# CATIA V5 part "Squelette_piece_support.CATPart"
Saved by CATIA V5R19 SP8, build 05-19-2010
Part number: Squelette_piece_support
Bounding box of the stored display mesh (mm): x -500 to 500, y 0 to 300, z 1175 to 1400
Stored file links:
  G:\EU_thinkMotion\CFAO_2010\MMS_groupe2\MMS_groupe2\OK\nrosalie\nrosalie_cfao_support_d_arme_legere_final\Squelette_piece_support.CATPart
  G:\EU_thinkMotion\CFAO_2010\MMS_groupe2\MMS_groupe2\OK\nrosalie\nrosalie_cfao_support_d_arme_legere_final\Squelette_Systeme_de_visee.CATPart
  G:\EU_thinkMotion\CFAO_2010\MMS_groupe2\MMS_groupe2\OK\nrosalie\nrosalie_cfao_support_d_arme_legere_final\nrosalie_Support_d_arme_legere.CATProduct
  G:\EU_thinkMotion\CFAO_2010\MMS_groupe2\MMS_groupe2\OK\nrosalie\nrosalie_cfao_support_d_arme_legere_final\Squelette_Colone.CATPart
  G:\EU_thinkMotion\CFAO_2010\MMS_groupe2\MMS_groupe2\OK\nrosalie\nrosalie_cfao_support_d_arme_legere_final\Bras.CATPart
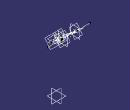
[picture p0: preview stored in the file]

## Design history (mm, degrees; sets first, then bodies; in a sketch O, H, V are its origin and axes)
External parameters (linked from other documents)
  External.Pourcentage_de_la_position_de_l_equilibrage_sur_la_piece_de_support_en_partant_axe_pivot_verticale = 10000 mm
  External.Distance_centre_cou_servant_et_pivot_bras_support = 150 mm
  External.Position_en_y_du_cou_du_servant = 300 mm
  `External.Hauteur_viseur_de_l'arme` = 1500 mm
  External.Distance_entre_les_yeux_du_servant_et_la_nuque_du_servant = 100 mm
  External.Longueur_liaison_pivot_colonne_systeme = 150 mm
Set1
  Point1 "Centre_cou_du_servant": (0, 300 {= External.Position_en_y_du_cou_du_servant}, 1400 {= `External.Hauteur_viseur_de_l'arme` -External.Distance_entre_les_yeux_du_servant_et_la_nuque_du_servant})
  Line1 "Axe_de_rotation_en_site": type Normal, RefPoint Point1, RefSkin yz-plane, Start -500, End 500
  Point2 "Centre_de_la_pivot": type OnCurve, Support Line1, RefPoint Point1, Length 150 {= External.Distance_centre_cou_servant_et_pivot_bras_support}
  Plane1 "Interphase_pivot_permettant _la_rotation_en_site": type Normal, Curve Line1, RefPoint Point2
  Point3 "Centre_liaison_pivot__systeme_de_visee": type OnCurve, Support Line7, RefPoint Point15, Length 75 {= 0.5*External.Longueur_liaison_pivot_colonne_systeme}
  Line2: type PtPt, FirstPoint Point1, SecondPoint Point3
  Point4: type OnCurve, Support Line2, Ratio 0.1 {= External.Pourcentage_de_la_position_de_l_equilibrage_sur_la_piece_de_support_en_partant_axe_pivot_verticale /100}
  Plane2: type OffsetPt, RefPlane xy-plane, RefPoint Point3
  Point5: type OnPlane, Support Plane2, RefPoint DatumPoint1, H -40, V 0, Direction (1, 0, 0)
  Point6: type OnCurve, Support Line1, RefPoint Point2, Length 10
  Line3: type PtPt, FirstPoint Point5, SecondPoint Point6
  Plane3: type Normal, Curve Line3, RefPoint Point5
  Plane4: type Normal, Curve Line3, RefPoint Point6
  Plane5: type 3Points, Element1 Point3, Element2 Point5, Element3 Point6
  Plane6: type 3Points, Element1 Point2, Element2 Point1, Element3 Point4
  Point7: type OnPlane, Support Plane6, RefPoint Point6, H 30, V 0, Direction (-1, 0, 0)
  Point8: type OnPlane, Support Plane6, RefPoint Point5, H 30, V 0, Direction (-1, 0, 0)
  Line4: type PtPt, FirstPoint Point8, SecondPoint Point7
  Point9: type OnCurve, Support Line4, Ratio 0.1 {= External.Pourcentage_de_la_position_de_l_equilibrage_sur_la_piece_de_support_en_partant_axe_pivot_verticale /100}
  Point10: type OnCurve, Support Line1, RefPoint Point1, Length 150 {= External.Distance_centre_cou_servant_et_pivot_bras_support}
  Point11: type OnCurve, Support Line1, RefPoint Point12, Length 30
  Point12: type OnCurve, Support Line1, RefPoint Point10, Length 10
  Plane7: type Normal, Curve Line1, RefPoint Point10
  Point13: type OnPlane, Support Plane2, RefPoint DatumPoint2, H 40, V 0, Direction (1, 0, 0)
  Line5: type PtPt, FirstPoint Point12, SecondPoint Point13
  Point14: type OnPlane, Support Plane2, RefPoint Point13, H 30, V 0, Direction (1, 0, 0)
  Line6: type PtPt, FirstPoint Point11, SecondPoint Point14
  Plane8: type Normal, Curve Line5, RefPoint Point13
  Plane9: type Normal, Curve Line5, RefPoint Point12
  Sketch1 on Plane7, origin (150, 0, 0), H (0, 1, 0), V (0, 0, 1)
    construction circle A1 centre (-150, 1220) radius 15
    point P1 (-150, 1220)
    spline S1 through (295.4323, 1314.2876) (-150.5609, 1234.9895) (-596.5542, 1279.5989)
    spline S2 through (304.5664, 1285.712) (-149.4391, 1205.0105) (-603.4446, 1250.4009)
    arc A2 centre (-600, 1265) radius 15 from (-596.5542, 1279.5989) to (-603.4446, 1250.4009) ccw
    point P2 (-600, 1265)
    arc A3 centre (300, 1300) radius 15 from (304.5664, 1285.712) to (295.4323, 1314.2876) ccw
    point P4 (-603.4446, 1250.4009)
    point P5 (-596.5542, 1279.5989)
    point P6 (295.4323, 1314.2876)
    point P7 (304.5664, 1285.712)
    reference projected point E1 (-150, 1220)
    reference projected point E2 (-600, 1265)
    reference projected point E3 (300, 1300)
    reference projected point E4 (300, 1300)
    point P8 (-150.5609, 1234.9895)
    point P9 (-149.4391, 1205.0105)
    point P10 (304.5664, 1285.712)
    point P11 (295.4323, 1314.2876)
    point P12 (-596.5542, 1279.5989)
    point P13 (-603.4446, 1250.4009)
    radius A2 = 15
    radius A1 = 15
    distance E3 A3 = 15
    tangency: S1 A1, A1 S2, A2 S2, S1 A2, S1 A3, S2 A3
    coincidence: P8 A1, P9 A1, P1 E1, P2 E2, P5 P12, P13 P4, P6 P11, P7 P10
    concentricity: A3 E4
  Sketch2 on Plane7, origin (150, 0, 1150.0001), H (0, 0, -1), V (0, 1, 0)
    line L1 (-150, 315) -> (-130, 315)
    line L2 (-130, 315) -> (-130, 285)
    line L3 (-130, 285) -> (-135, 285)
    line L4 (-150, 285) -> (-150, 315)
    line L5 (-145.2686, 285) -> (-69.4353, -40)
    point P6 (-69.4353, -40)
    line L6 (-135, 285) -> (-59.1667, -40)
    point P8 (-59.1667, -40)
    line L7 (-59.1667, -40) -> (-59.1667, -630)
    point P9 (-59.1667, -40)
    line L8 (-69.4353, -40) -> (-69.4353, -640)
    point P11 (-69.4353, -40)
    line L9 (-145.2686, 285) -> (-150, 285)
    construction line L10 (-130, 247.183) -> (-130, 159.7527)
    line L11 (-69.4353, -640) -> (-59.1667, -640)
    axis line L12 (403.9745, -40) -> (-248.0728, -40)
    reference intersected line E1 through (-150, 0) direction (0, 1)
    reference projected point E2 (0, 0)
    reference intersected line E3 through (-150, 0) direction (0, 1)
    reference projected line E4 (-500, 300) -> (500, 300)
    reference projected line E5 (-500, 300) -> (500, 300)
    reference projected line E6 (-88.8296, -5.016) -> (-160, 300)
    line L13 (130, 315) -> (150, 315)
    line L14 (150, 315) -> (150, 285)
    line L15 (150, 285) -> (145.2686, 285)
    line L16 (130, 315) -> (130, 285)
    point P21 (130, 285)
    line L17 (130, 285) -> (135, 285)
    line L18 (135, 285) -> (59.1667, -40)
    line L19 (59.1667, -630) -> (59.1667, -40)
    line L20 (59.1667, -640) -> (69.4353, -640)
    line L21 (69.4353, -640) -> (69.4353, -40)
    line L22 (69.4353, -40) -> (145.2686, 285)
    reference projected line E7 (0, 300) -> (0, 0)
    reference projected line E8 (0, 300) -> (0, 0)
    reference projected line E9 (0, 300) -> (0, 0)
    reference projected line E10 (0, 300) -> (0, 0)
    reference projected line E11 (0, 300) -> (0, 0)
    reference projected line E12 (0, 300) -> (0, 0)
    reference projected line E13 (0, -600) -> (0, 200)
    reference projected line E14 (0, 300) -> (0, 0)
    reference projected line E15 (0, 300) -> (0, 0)
    line L23 (-59.1667, -630) -> (59.1667, -630)
    line L24 (-59.1667, -640) -> (59.1667, -640)
    distance E2 L12 = 40
    distance L2 E3 = 20
    distance L6 L5 = 10
    distance L1 E5 = 15
    distance L11 L12 = 600
    length L3 = 5
    distance L23 L24 = 10
    coincidence: L4 E1, P6 P11, P9 P8, P8 L12, L12 P6, L3 L9, P21 L15
    symmetry: L1 L9 E4, L13 L1 E7, L16 L2 E8, L14 L4 E9, L17 L3 E10, L18 L6 E11, L22 L5 E12, L19 L7 E13, L8 L21 E14, L20 L11 E15
    parallelism: L5 E6, L8 L7
    horizontal: L12 H, L13 H, L15 H, L17 H, L20 H, L23 H, L24 H
    vertical: L7 V, L14 V, L16 V, L19 V, L21 V
Set2
  Line7 "Axe_vertical_colonne": linked copy from another document
  Point15 "Centre_plan_limite_superieur_colonne": linked copy from another document
  DatumPoint1: linked copy from another document
  DatumPoint2: linked copy from another document
Body1 (main body)
  SolidCombine1: FirstComponentProfile Sketch1, FirstComponentDirection Sketch1, SecondComponentProfile Sketch2, SecondComponentDirection Sketch2, deactivated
